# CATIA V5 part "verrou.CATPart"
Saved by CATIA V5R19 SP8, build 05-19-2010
Part number: verrou
Bounding box of the stored display mesh (mm): x -26.1 to 14.5, y -118.505 to 29.236, z -14.312 to 4.919
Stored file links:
  G:\EU_thinkMotion\CFAO_2010\MMS_groupe2\MMS_groupe2\A reprendre\rbouchet\rbouchet_Catia\verrou.CATPart
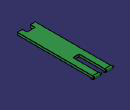
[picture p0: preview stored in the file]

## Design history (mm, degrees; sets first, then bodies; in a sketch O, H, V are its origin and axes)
Body1 (main body)
  Sketch1 on yz-plane, origin (0, 0, 0), H (0, 1, 0), V (0, 0, 1)
    line L1 (-26, 0) -> (24, 0)
    point P1 (-26, 0)
    arc A1 centre (25.9469, 0.4578) radius 2 from (24, 0) to (25.8505, -1.5399) ccw
    point P3 (25.9469, 0.4578)
    point P4 (25.8505, -1.5399)
    line L2 (25.8505, -1.5399) -> (27.2269, -0.4591)
    point P5 (25.8505, -1.5399)
    line L3 (25, 4.5) -> (-26, 4.5)
    point P7 (25, 4.5)
    arc A2 centre (26.4946, 2.1916) radius 2.75 from (27.2269, -0.4591) to (25, 4.5) ccw
    point P10 (25, 4.5)
    line L4 (-26, 4.5) -> (-26, 0)
    distance P3 A1 = 2
    radius A2 = 2.75
    distance L3 L1 = 4.5
    length L2 = 1.75
    length L3 = 51
    length L1 = 50
    coincidence: P1 H, P5 A1, P5 P4, P7 P10
    horizontal: L1 H, L3 H
    vertical: L4 V
  Pad1: profile Sketch1, direction (1, 0, 0), length 11.5
  Sketch2 on end face of Pad1, origin (11.5, 0, 0), H (0, 1, 0), V (0, 0, 1)
    circle A1 centre (26.4946, 2.1916) radius 1.5
    point P1 (26.4946, 2.1916)
    reference projected arc E1 centre (26.4946, 2.1916) radius 2.75 from (27.2269, -0.4591) to (25, 4.5) ccw from edge [face of Pad1 from Sketch1.A2 | end face of Pad1]
    radius A1 = 1.5
    distance P1 E1 = 2.75
  Pad2: profile Sketch2, direction (1, 0, 0), length 3, opposite side length 14.5
  Fillet1: radius 0.2, on edge [face of Pad1 from Sketch1.L3 | face of Pad1 from Sketch1.A2]; edge [end face of Pad1 | face of Pad2 from Sketch2.A1]; edge [face of Pad2 from Sketch2.A1 | start face of Pad1]; edge [face of Pad1 from Sketch1.A2 | face of Pad1 from Sketch1.L2]; edge [face of Pad1 from Sketch1.A1 | face of Pad1 from Sketch1.L1]; edge [start face of Pad1 | face of Pad1 from Sketch1.L3]; edge [start face of Pad1 | face of Pad1 from Sketch1.L1]; edge [face of Pad1 from Sketch1.L3 | end face of Pad1]; edge [face of Pad1 from Sketch1.L1 | end face of Pad1]
  Fillet2: radius 0.2, on edge [start face of Pad1 | face of Pad1 from Sketch1.A2]; edge [face of Fillet1 | start face of Pad1] (x2); edge [face of Fillet1 | end face of Pad1] (x2); edge [face of Pad1 from Sketch1.A2 | end face of Pad1]; edge [face of Pad1 from Sketch1.A1 | end face of Pad1]; edge [start face of Pad1 | face of Pad1 from Sketch1.A1]
  Plane1: type Offset, RefPlane yz-plane, Offset 5.8, reversed
  Mirror1: of Pad1, Pad2, Fillet1, Fillet2, about Plane1
  Sketch3 on Plane1, origin (-5.8, 0, 0), H (0, 1, 0), V (0, 0, 1)
    line L1 (-118.5054, 4.5) -> (-23.5054, 4.5)
    line L2 (-23.5054, 4.5) -> (-23.5054, 0)
    line L3 (-23.5054, 0) -> (-118.5054, 0)
    line L4 (-118.5054, 0) -> (-118.5054, 4.5)
    reference projected point E1 (26.4946, 2.1916) from axis of face of Pad2 from Sketch2.A1
    reference intersected line E2 through (0, 4.5) direction (-1, 0) from face of Pad1 from Sketch1.L3
    length L4 = 4.5
    distance E1 L2 = 50
    length L1 = 95
    distance L1 E2 = 0
    horizontal: L1 H, L3 H
    vertical: L2 V, L4 V
  Pad3: profile Sketch3, direction (1, 0, 0), length 17.3, mirrored extent
  Fillet3: radius 0.2, on edge [face of Pad3 | face of Pad3] (x4); edge [face of Pad3 | face of Pad3 from Sketch3.L2]; edge [face of Pad3 from Sketch3.L2 | face of Pad3]; edge [face of Pad3 from Sketch3.L2 | start face of Pad1]; edge [face of Mirror1 | face of Pad3 from Sketch3.L2]; edge [face of Pad3 | face of Pad3 from Sketch3.L4] (x2); edge [face of Pad3 from Sketch3.L4 | face of Pad3] (x2)
  Sketch4 on face of Pad3, origin (0, 0, 4.5), H (1, 0, 0), V (0, 1, 0)
    line L1 (-13.3, -109.5054) -> (1.7, -109.5054)
    line L2 (1.7, -109.5054) -> (1.7, -118.5054)
    line L3 (1.7, -118.5054) -> (-13.3, -118.5054)
    line L4 (-13.3, -118.5054) -> (-13.3, -109.5054)
    reference intersected line E1 (11.5, -118.5054) -> (-23.1, -118.5054) from face of Pad3 from Sketch3.L4
    reference intersected line E2 (-23.1, -26) -> (-23.1, 27.9891) from face of Pad3
    length L1 = 15
    length L4 = 9
    distance L3 E1 = 0
    distance L4 E2 = 9.8
    horizontal: L1 H, L3 H
    vertical: L2 V, L4 V
  Pocket1: profile Sketch4, direction (0, 0, -1), through (limit type 6)
  Fillet4: radius 0.2, on edge [face of Pad3 from Sketch3.L4 | face of Pocket1 from Sketch4.L4]; edge [face of Pocket1 from Sketch4.L4 | face of Pocket1 from Sketch4.L1]; edge [face of Pocket1 from Sketch4.L4 | face of Pad3]; edge [face of Pad3 | face of Pocket1 from Sketch4.L4]; edge [face of Pad3 | face of Pocket1 from Sketch4.L1] (x2); edge [face of Pad3 | face of Pocket1 from Sketch4.L2] (x2); edge [face of Pocket1 from Sketch4.L2 | face of Pad3 from Sketch3.L4]; edge [face of Pocket1 from Sketch4.L1 | face of Pocket1 from Sketch4.L2]
  Sketch5 on face of Pad3, origin (0, 0, 0), H (1, 0, 0), V (0, -1, 0)
    line L1 (-8.8, 103.5054) -> (-2.8, 103.5054)
    line L2 (-2.8, 103.5054) -> (-2.8, 96.6304)
    line L3 (-2.8, 96.6304) -> (-8.8, 96.6304)
    line L4 (-8.8, 96.6304) -> (-8.8, 103.5054)
    reference intersected line E1 (1.7, 109.5054) -> (-13.3, 109.5054) from face of Pocket1 from Sketch4.L1
    reference intersected line E2 (-23.1, -28.1557) -> (-23.1, 26) from face of Pad3
    length L1 = 6
    length L2 = 6.875
    distance E1 L1 = 6
    distance L4 E2 = 14.3
    horizontal: L1 H, L3 H
    vertical: L2 V, L4 V
  Pad4: profile Sketch5, direction (0, 0, -1), length 14.312
  Fillet5: radius 1, on edge [face of Pad4 from Sketch5.L1 | face of Pad4 from Sketch5.L2]; edge [face of Pad4 from Sketch5.L4 | face of Pad4 from Sketch5.L1]; edge [face of Pad4 from Sketch5.L3 | face of Pad4 from Sketch5.L4]; edge [face of Pad4 from Sketch5.L2 | face of Pad4 from Sketch5.L3]; edge [face of Pad3 | face of Pad4 from Sketch5.L2]; edge [face of Pad3 | face of Pad4 from Sketch5.L1]; edge [face of Pad3 | face of Pad4 from Sketch5.L4]; edge [face of Pad3 | face of Pad4 from Sketch5.L3]
  RectPattern1: of Pad4, Fillet5, direction 1 instances 6, spacing 12.875, along edge [face of Fillet3 | face of Pad3]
